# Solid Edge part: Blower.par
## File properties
Author: CADCIM
Template: NORMENG.PAR
Last saved by: Cadcim
Revision: 7
Application: Solid Edge
Accuracy: 0.99
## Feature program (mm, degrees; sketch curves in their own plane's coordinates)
sketch for "unnamed RevolvedProtrusion 1" #1 plane through (0, 0, 0) normal (0, -1, 0) x-axis (1, 0, 0)
  line (0, 171.45) -> (139.7, 171.45)
  line (139.7, 171.45) -> (139.7, 165.1)
  line (139.7, 165.1) -> (0, 165.1)
  line (0, 165.1) -> (0, 171.45)
sketch for "unnamed RevolvedProtrusion 1" #2 plane through (0, 0, 0) normal (0, -1, 0) x-axis (1, 0, 0)
  line (0, 0) -> (0, 0)
  line (0, 0) -> (0, 0)
  line (139.7, 0) -> (139.7, -12.7)
  line (139.7, -12.7) -> (38.1, -12.7)
  line (38.1, -12.7) -> (38.1, -76.2)
  line (38.1, -76.2) -> (0, -76.2)
  line (0, -76.2) -> (0, 0)
  line (0, 0) -> (139.7, 0)
  dimension (linear) = 38.1
  dimension (linear) = 139.7
revolve "unnamed RevolvedProtrusion 1" add finite 360 deg
sketch for "unnamed Protrusion 1" plane through (0, 0, 0) normal (0, 0, 1) x-axis (1, 0, 0)
  line (76.708, 0) -> (139.7, 0)
  line (127.6948, -46.4771) -> (131.2751, -47.7802)
  line (76.708, -6.35) -> (135.0219, -6.35)
  line (76.708, 0) -> (76.708, -6.35)
  dimension (linear) = 127.6948
  dimension (linear) = 76.708
extrude "unnamed Protrusion 1" add through along +normal
pattern "unnamed Pattern 1" of "unnamed Protrusion 1"
extrude "unnamed Protrusion 2" add through
extrude "unnamed Protrusion 3" add through
extrude "unnamed Protrusion 4" add through
extrude "unnamed Protrusion 5" add through
extrude "unnamed Protrusion 6" add through
sketch for "unnamed Hole 1" plane through (0, 0, -76.2) normal (0, 0, -1) x-axis (1, 0, 0)
hole "unnamed Hole 1" through
sketch for "ExtrudedCutout_1" plane through (0, 0, 171.45) normal (0, 0, 1) x-axis (0, -1, 0)
extrude "ExtrudedCutout_1" cut finite 6.35 along -normal
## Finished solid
Body 1: solid body, 50 faces, 139 edges, 84 vertices.
  Faces by surface: plane 40, cylinder 10
  Edges by curve: line 96, circle 43
Bounding box of the edges (mm): 279.400 x 279.400 x 247.650, from (-139.7, -139.7, -76.2) to (139.7, 139.7, 171.45).
Cylindrical faces by radius (mm): R19.05 x1, R38.1 x1, R101.6 x1, R131.6115 x6, R139.7 x1
Planar faces by outward normal: +x 1, +y 2, +z 8, -x 1, -y 2, -z 8, oblique 18
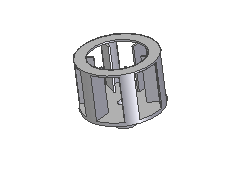
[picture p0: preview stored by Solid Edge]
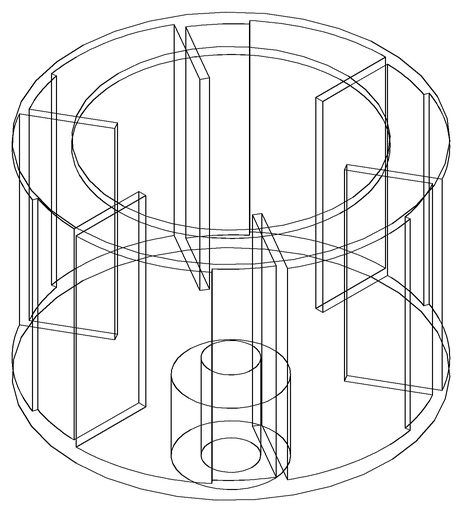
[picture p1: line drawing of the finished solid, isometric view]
